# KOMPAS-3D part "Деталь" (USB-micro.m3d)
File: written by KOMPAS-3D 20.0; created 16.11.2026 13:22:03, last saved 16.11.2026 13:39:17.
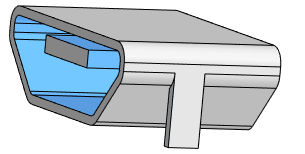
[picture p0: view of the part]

Document properties: Полное имя файла: D:\RicWork\Project-EPS32\box_compas\разъемы\USB-micro.m3d

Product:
- Part/product: Деталь
    Масса: 0.000213803
  - Body: Тело 1
      Масса: 0.000207339

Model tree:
1. Эскиз:1
2. Элемент выдавливания:1
     Расстояние 1 = 4.7
3. Фаска:1  (with: Элемент выдавливания:1)
     Угол = 45; Длина 1 = 1.5; Длина 2 = 1.5
4. Скругление:1  (with: Элемент выдавливания:1, Фаска:1)
     Радиус = 0.5
5. Эскиз:3  (with: Элемент выдавливания:1, Фаска:1, Скругление:1)
6. Элемент выдавливания:2
     Расстояние 2 = 4.5
7. Эскиз:4  (with: Элемент выдавливания:1, Скругление:1, Фаска:1)
8. Элемент выдавливания:3
     Расстояние 2 = 0.25
9. Смещенная плоскость:1  (with: Элемент выдавливания:1)
     Расстояние = 3.5
10. Зеркальный массив:1
11. Экземпляр ( 1 )
12. Экземпляр ( 2 )  (with: Элемент выдавливания:3)
13. Эскиз:5  (with: Элемент выдавливания:1)
14. Элемент выдавливания:4
     Расстояние 1 = 0.5
15. Массив по сетке:1  (with: Элемент выдавливания:4, Эскиз:5)  (5 pattern instances)
     Шаг 1 = 0.5; Угол раствора = 90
